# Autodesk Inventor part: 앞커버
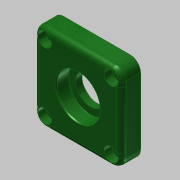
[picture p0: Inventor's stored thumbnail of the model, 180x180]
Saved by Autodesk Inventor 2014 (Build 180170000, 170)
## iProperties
Created: 2018-07
Part Number: 앞커버
Material: 알루미늄 6061
Document SubType Name: Modeling
Designer: mduedu
Density: 1 g/cm^3
Appearance: 매끄러움 - 짙은 산림 녹색
Author: mduedu
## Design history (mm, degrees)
sketch "스케치1"
  geometry: C1 r 16 at (0, 0); 1 further point
  constraints: 1 centre point, 1 coincident
  dimensions: "d0" = 32 diameter of C1
extrude "돌출1" new body sketch "스케치1" distance "d1" = 3; taper "d2" = 0 deg
sketch "스케치2"
  geometry: L1 (-25, -25)-(25, -25); L2 (25, -25)-(25, 25); L3 (25, 25)-(-25, 25); L4 (-25, 25)-(-25, -25); L5 (-25, -25)-(25, 25); L6 (25, -25)-(-25, 25); 1 further point
  constraints: 12 end point, 2 midpoint, 2 parallel, 1 horizontal, 1 perpendicular
  dimensions: "d3" = 50 distance of L3.end L2.end; "d4" = 50 distance of L2.end L1.end
extrude "돌출2" join sketch "스케치2" distance "d5" = 11; taper "d6" = 0 deg
hole "구멍1" diameter "d9" = 25; stored, may be unused: countersink angle "d13" = 90 deg, drill point angle "d15" = 0 deg; dims "d7" = 10, "d8" = 10, "d10" = 6, "d11" = 4, "d12" = 2, "d14" = 3
sketch "스케치3"
  geometry: C1 r 12.5 at (0, 0); 1 further point
  constraints: 1 centre point, 1 coincident
  dimensions: "d16" = 25 diameter of C1
extrude "돌출3" cut sketch "스케치3" distance "d17" = 7.3; taper "d18" = 0 deg
sketch "스케치4"
  geometry: C1 r 8.5 at (0, 0); 1 further point
  constraints: 1 centre point, 1 coincident
  dimensions: "d19" = 17 diameter of C1
extrude "돌출4" cut sketch "스케치4" stored distance "d20" = 7.3; taper "d21" = 0 deg
chamfer "모따기1" distance "d22" = 0.7; stored, may be unused: second distance "d23" = 2, angle "d24" = 30 deg
fillet "모깎기1" dims "d25" = 0.3
fillet "모깎기2" dims "d26" = 3
fillet "모깎기3" dims "d27" = 6
sketch "스케치5"
  geometry: L1 (25, -19)-(25, 19) reference; L2 (19, 25)-(-19, 25) reference; L3 (-25, 19)-(-25, -19) reference; L4 (-19, -25)-(19, -25) reference; C1 r 12.904 at (0, 0) reference; A1 r 6 centre (19, -19) between (19, -25) and (25, -19) reference; A2 r 6 centre (19, 19) between (25, 19) and (19, 25) reference; A3 r 6 centre (-19, 19) between (-19, 25) and (-25, 19) reference; A4 r 6 centre (-19, -19) between (-25, -19) and (-19, -25) reference; 5 further points
  constraints: 4 coincident
hole "구멍2" sketch "스케치5" at (-19, 19), (19, 19), (19, -19), (-19, -19) diameter "d28" = 4.5; stored, may be unused: countersink angle "d32" = 90 deg, drill point angle "d34" = 0 deg; dims "d29" = 6, "d30" = 8, "d31" = 4.6, "d33" = 3
fillet "모깎기4" dims "d35" = 3
chamfer "모따기2" distance "d36" = 1; stored, may be unused: second distance "d37" = 2, angle "d38" = 45 deg
node "솔리드1"
node "투영된 루프1"
